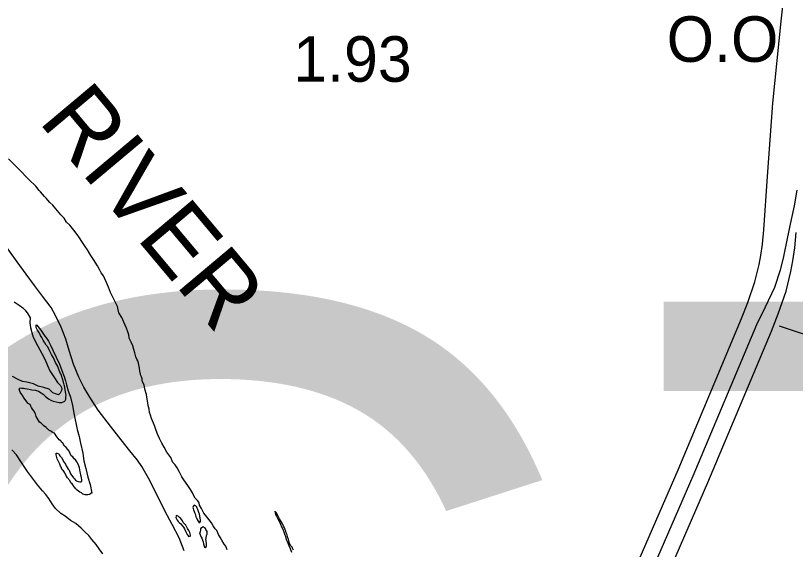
# Model space of a CAD drawing. Extents: x 31699 to 244310, y -8841 to 11474.
# Drawn here: x 103265.1 to 103747.3, y 0.3 to 330.2 of the extents above; entities that cross this region are included whole.
import ezdxf

# ---------------------------------------------------------------- set-up
doc = ezdxf.new("R2010")
doc.units = 0
for name, color, linetype in [('B_Logo', 7, 'Continuous'), ('R_Border', 7, 'Continuous'), ('R_Draft', 7, 'Continuous'), ('R_Logo', 7, 'Continuous'), ('R_XS_EARTHWORK_STAGE1', 7, 'Continuous'), ('R_XS_EARTHWORK_STAGE2', 7, 'Continuous'), ('S_WALL', 7, 'Continuous'), ('S_WALL_ANNOT', 7, 'Continuous')]:
    doc.layers.add(name, color=color, linetype=linetype)

msp = doc.modelspace()

# ---------------------------------------------------------------- linework, layer by layer
at = {"layer": 'B_Logo'}
msp.add_lwpolyline([(103748.16, 222.36), (103746.61, 212.64), (103744.7, 204.12), (103742.25, 192.44), (103740.05, 181.24), (103737.87, 172.85), (103734.47, 162.16), (103728.56, 149.95), (103723.29, 139.09), (103683.94, 45.46), (103620.47, -100.58)], dxfattribs=at)
at = {"layer": 'R_Draft'}
for points in [[(103277.65, 224.72), (103273.23, 228.97), (103266.96, 235.45), (103260.64, 241.73)], [(103283.04, 218.49), (103281.75, 219.93), (103280.52, 221.24), (103279.63, 222.16), (103277.65, 224.72)], [(103390.6, 9.5), (103389.55, 11.89), (103388.52, 13), (103387.35, 14.91), (103386.18, 16.69), (103384.81, 18.54), (103383.38, 20.31), (103381.59, 22.74), (103380.07, 25.45), (103378.76, 27.63), (103378.82, 27.7), (103378.67, 28.89), (103378.46, 29.42), (103377.57, 30.47), (103376.14, 31.91), (103375.17, 33.7), (103374.41, 35.15), (103373.23, 37.2), (103372.06, 39.04), (103370.27, 41.74), (103369.24, 43.33), (103368, 45.04), (103367.03, 46.75), (103366.2, 48.34), (103364.95, 50.65), (103363.78, 52.56), (103362.35, 53.94), (103361.02, 57.05), (103358.56, 60.34), (103356.96, 63.38), (103355.44, 65.88), (103354.05, 68.79), (103353, 71.04), (103352.08, 73.83), (103351.23, 76.15), (103350.45, 78.34), (103349.19, 81.19), (103348.49, 83.18), (103347.98, 84.97), (103347.61, 86.9), (103347.16, 89.16), (103346.8, 90.69), (103346.57, 92.09), (103346.32, 94.29), (103345.95, 96.08), (103345.02, 99.27), (103344.63, 102.07), (103343.66, 103.92), (103343.37, 104.92), (103343.29, 105.65), (103342.86, 106.98), (103342.64, 107.84), (103342.43, 108.64), (103341.86, 110.43), (103341.75, 112.23), (103341.6, 113.37), (103341.09, 115.43), (103340.66, 116.75), (103340.1, 117.94), (103339.41, 119.33), (103338.76, 121.72), (103338.25, 123.72), (103337.67, 126.04), (103336.56, 128.29), (103335.37, 130.74), (103335.06, 132.8), (103334.77, 134.2), (103333.71, 136.99), (103332.87, 138.9), (103331.97, 140.62), (103330.84, 143.61), (103328.92, 146.44), (103328.04, 150.36), (103326.5, 153.74), (103325.32, 156.18), (103323.86, 159.03), (103322.45, 162.4), (103321.33, 165.32), (103320.28, 167.5), (103319.38, 169.35), (103318.07, 171.2), (103316.97, 173.24), (103315.72, 175.62), (103313.3, 179.51), (103311.72, 181.95), (103309.65, 185.45), (103308.21, 187.56), (103306.15, 190.52), (103304.57, 192.76), (103303.25, 195), (103301.13, 197.63), (103298.54, 200.58), (103296.57, 202.54), (103295.05, 204.98), (103293.14, 207.08), (103290.07, 210.76), (103288.15, 213.05), (103286.25, 214.68), (103285.02, 216.2), (103284.06, 217.38), (103283.04, 218.49)], [(103264.2, 153.34), (103267.32, 151.13), (103269.55, 149.64), (103270.98, 148.14), (103272.62, 145.9), (103274.01, 143.39), (103274, 140.32), (103274.26, 137.45), (103275.06, 134.39), (103276.05, 131.41), (103278.56, 126.31), (103281.33, 121.43), (103283.41, 117.46), (103284.81, 114.02), (103286.28, 110.58), (103289.1, 106.23), (103290.96, 103.46), (103292.87, 101.5), (103293.77, 99.98), (103293.59, 98.57), (103292.7, 96.88), (103291.59, 95.85), (103290.44, 96.3), (103288.03, 97.11), (103285.85, 99.21), (103282.63, 100.34), (103279.15, 101.07), (103276.12, 102.54), (103272.1, 103.59), (103269.29, 104), (103266.6, 105.34), (103263.23, 107.21)], [(103292.43, 109.84), (103291.5, 112.76), (103291.01, 113.82), (103289.84, 115.8), (103289.14, 117.32), (103288.58, 118.58), (103287.4, 120.69), (103285.94, 123.67), (103285.04, 125.38), (103284.09, 126.43), (103283.12, 128.02), (103282.22, 129.6), (103281.26, 131.18), (103280.5, 132.44), (103279.8, 133.82), (103278.69, 135.87), (103277.86, 137.46), (103277.76, 138.99), (103278.16, 138.93), (103280.63, 135.85), (103283.17, 132.09), (103284.13, 130.91), (103285.44, 128.87), (103286.41, 126.82), (103286.62, 126.42), (103288.08, 123.31), (103290.24, 119.08), (103292.26, 114.65), (103293.67, 110.93), (103295.22, 107.03), (103295.94, 104.37), (103296.59, 101.98), (103297.6, 98.19), (103299.01, 94.28), (103300.32, 89.29), (103301.15, 84.5), (103303.16, 74.45), (103304.51, 70.07), (103305.33, 65.88), (103306.66, 59.83), (103307.36, 54.96), (103308.59, 50.31), (103309.83, 44.93), (103311.2, 40.28), (103312.3, 35.02)], [(103277.31, 83.99), (103276.33, 85.91), (103275.58, 87.02), (103274.96, 87.95), (103274.47, 88.87), (103274.12, 89.87), (103272.91, 90.51), (103270.72, 93.2), (103269.06, 96.04), (103268.03, 97.35), (103267.26, 99.21), (103267.71, 100.15), (103268.98, 99.91), (103269.98, 99.87), (103270.85, 99.69), (103272.19, 99.45), (103273.52, 99.21), (103275.13, 98.98), (103277.4, 98.76), (103279.35, 98.06), (103280.97, 97.03), (103282.12, 96.19), (103283.54, 94.81), (103285.37, 93.32), (103286.79, 92.48), (103288.4, 91.91), (103292.02, 90.99), (103293.75, 91.09), (103295.6, 91.86), (103296.17, 93.15), (103296.21, 94.55), (103296.33, 95.29), (103296.23, 96.56), (103295.85, 98.95), (103295.49, 100.35), (103295.34, 101.35), (103295.19, 101.95), (103294.82, 103.61), (103294.18, 105.6), (103293.54, 107.66), (103292.77, 109.18), (103292.43, 109.84), (103292.08, 110.57)], [(103312.11, 34.95), (103311.05, 34.39), (103310.72, 34.12), (103309.73, 33.9), (103308.66, 33.94), (103308.13, 34), (103306.92, 34.31), (103306.65, 34.43), (103305.9, 35.29), (103304.9, 35.53), (103304.02, 36.31), (103303.27, 36.9), (103302.45, 37.75), (103301.5, 38.67), (103300.88, 39.59), (103299.99, 40.84), (103299.31, 41.43), (103298.55, 42.75), (103297.94, 43.4), (103297.73, 43.8), (103297.18, 44.59), (103296.22, 46.1), (103295.45, 47.56), (103294.69, 48.88), (103293.95, 49.53), (103293.59, 50.39), (103293.45, 50.79), (103292.97, 51.65), (103292.54, 52.91), (103292.13, 53.7), (103291.64, 54.63), (103291.29, 55.35), (103290.74, 56.21), (103290.52, 57.14), (103290.23, 58.61), (103290.15, 59), (103290.13, 59.81), (103290.87, 59.82), (103291.67, 59.44), (103292.09, 58.78), (103292.5, 58.12), (103293.05, 57.46), (103293.52, 57.01), (103294.28, 55.69), (103294.77, 54.56), (103296.01, 52.92), (103296.36, 51.99), (103297.54, 49.94), (103298.15, 49.15), (103298.5, 48.56), (103298.85, 47.5), (103299.13, 46.97), (103299.95, 45.98), (103300.98, 44.54), (103301.46, 43.94), (103302.08, 43.02), (103302.75, 42.57), (103303.89, 42.26), (103304.83, 41.95), (103305.36, 41.96), (103306.02, 42.31), (103306, 43.31), (103305.78, 44.44), (103305.62, 45.5), (103305.54, 46.17), (103305.25, 47.37), (103305.03, 48.3), (103304.74, 49.43), (103304.52, 50.76), (103304.29, 51.89), (103303.87, 52.88), (103303.04, 54.4), (103302.15, 55.52), (103301.4, 56.17), (103300.58, 57.42), (103299.56, 58.14), (103298.87, 59.53), (103298.24, 60.92), (103297.35, 61.97), (103296.39, 63.28), (103295.44, 64.13), (103294.41, 65.84), (103293.59, 66.63), (103293.11, 67.29), (103292.1, 68), (103291.35, 68.85), (103290.86, 69.71), (103290.18, 70.5), (103289.49, 71.42), (103289.08, 72.15), (103288.47, 72.4), (103287.67, 72.78), (103286.79, 73.37), (103285.64, 74.01), (103283.94, 75.51), (103282.52, 76.62), (103280.96, 78.25), (103279.81, 78.96), (103278.49, 81.41), (103277.74, 82.46), (103277.31, 83.99)], [(103319.08, -2.39), (103316.75, 0.57), (103314.83, 3.2), (103312.24, 6.29), (103310.32, 8.79), (103307.87, 11.21), (103305.63, 13.3), (103302.3, 16.36), (103299.13, 18.03), (103295.81, 20.77), (103293.04, 22.45), (103289.78, 25.52), (103287.72, 28.48), (103285.59, 31.71), (103283.74, 34.14), (103281.83, 36.37), (103278.68, 40.18), (103276.83, 42.68), (103274.36, 45.97), (103272.45, 48.4), (103268.8, 53.94), (103265.7, 58.68), (103262.7, 61.89)], [(103379.05, 16.94), (103379.43, 17.55), (103379.48, 18.42), (103379.26, 19.75), (103379.11, 20.35), (103378.96, 21.08), (103378.74, 22.01), (103378.46, 23.01), (103378.17, 23.67), (103377.96, 24.2), (103377.75, 24.87), (103377.54, 25.33), (103377.47, 25.66), (103377.19, 26.26), (103376.91, 26.72), (103376.57, 27.05), (103376.17, 27.24), (103375.63, 27.49), (103375.04, 27.08), (103374.79, 26.21), (103375.01, 25.47), (103375.22, 24.68), (103375.51, 23.75), (103375.79, 23.15), (103376.14, 22.22), (103376.35, 21.49), (103376.86, 19.7), (103376.92, 19.77), (103377.69, 18.38), (103378.79, 16.4)], [(103373.04, 7.99), (103373.28, 9.13), (103372.91, 10.73), (103372.15, 11.98), (103371.4, 13.1), (103370.29, 15.15), (103369.54, 16.07), (103368.79, 16.92), (103368.3, 17.98), (103367.34, 19.3), (103366.46, 20.01), (103366.11, 20.47), (103365.57, 20.8), (103364.37, 21.17), (103364.37, 20.84), (103364.26, 20.03), (103364.68, 19.11), (103365.03, 18.24), (103365.64, 17.52), (103366.32, 16.8), (103367.27, 16.02), (103367.82, 15.23), (103368.91, 14.05), (103369.6, 12.93), (103370.44, 11.21), (103370.79, 10.22), (103371.21, 9.49), (103371.82, 8.63), (103372.3, 7.98)], [(103436.91, -0.19), (103436.35, 1), (103436.14, 1.59), (103435.25, 2.51), (103434.56, 3.97), (103434.13, 5.29), (103433.84, 6.42), (103433.34, 7.95), (103432.98, 9.21), (103432.42, 10.47), (103432.2, 11.47), (103431.85, 12.26), (103431.29, 13.65), (103430.8, 14.64), (103430.45, 15.57), (103429.9, 16.43), (103429.28, 17.48), (103428.38, 19.07), (103427.55, 20.72), (103426.78, 22.04), (103426.16, 23.03), (103425.42, 23.82), (103425.64, 22.75), (103425.79, 21.82), (103426.41, 20.76), (103426.76, 20.04), (103427.18, 19.11), (103428.28, 17.26), (103428.84, 15.94), (103429.55, 14.22), (103430.37, 12.83), (103430.88, 11.17), (103431.37, 9.91), (103431.94, 8.25), (103432.44, 6.46), (103433.34, 4.67), (103434.12, 2.69), (103434.82, 0.83), (103435.67, -1.56)], [(103382.5, 1.31), (103383.22, 2.33), (103383.25, 4), (103382.73, 6.46), (103382.98, 7.4), (103383.21, 8.81), (103383.59, 9.76), (103383.5, 11.22), (103383.15, 11.95), (103382.8, 12.54), (103382.59, 13.14), (103381.85, 13.59), (103381.17, 14.31), (103380.38, 13.83), (103379.92, 13.55), (103379.46, 13.01), (103379.54, 12.27), (103379.3, 11.2), (103378.92, 10.46), (103379.27, 9.26), (103379.48, 8.8), (103379.9, 7.87), (103380.18, 7.14), (103380.74, 5.89), (103381.03, 5.02), (103381.39, 3.63), (103381.75, 2.3), (103381.96, 1.63), (103382.64, 1.38)], [(103395.93, -0.07), (103395.08, 2.18), (103394.05, 3.56), (103392.67, 5.87), (103391.91, 7.33), (103390.6, 9.5)]]:
    msp.add_lwpolyline(points, dxfattribs=at)
at = {"layer": 'R_Logo'}
msp.add_lwpolyline([(103369.42, -0.57), (103366.25, 7.45), (103362.02, 15.64), (103357.58, 23.76), (103352.79, 33.28), (103347.23, 44.26), (103343.21, 51.52), (103340.4, 55.34), (103335.75, 61.25), (103330.34, 68.02), (103323.84, 76.5), (103316.1, 86.36), (103311.01, 94.27), (103307.21, 100.6), (103304.22, 106.68), (103300.99, 114.77), (103298.15, 123.26), (103296.14, 130.23), (103293.18, 137.72), (103289.77, 144.86), (103287.2, 149.82), (103281.79, 156.85), (103276.79, 163.3), (103271.58, 170.33), (103266.02, 178.1), (103260.33, 186.13)], dxfattribs=at)
at = {"layer": 'R_XS_EARTHWORK_STAGE1'}
msp.add_line((103754.23, 132.58), (103737.6, 138.32), dxfattribs=at)
at = {"layer": 'R_XS_EARTHWORK_STAGE2'}
for points in [[(103521.84, -307.39), (103540.82, -258.86), (103545.53, -248.33), (103550.26, -237), (103554.27, -226.65), (103559.44, -214.4), (103611.32, -96.55), (103674.75, 49.39), (103714.07, 142.97), (103717.92, 152.82), (103722.33, 165.55), (103724.97, 176.28), (103726.06, 181.98), (103727.08, 189.01), (103727.84, 197.81), (103730.08, 230.83), (103733.36, 276.02), (103738.47, 326.72), (103740.61, 345.27)], [(103541.68, -311.57), (103559.27, -266.59), (103563.89, -256.27), (103568.82, -244.47), (103572.81, -234.15), (103577.81, -222.32), (103629.62, -104.6), (103693.14, 41.53), (103732.51, 135.22), (103736.69, 145.9), (103741.53, 159.87), (103744.52, 172.01), (103745.79, 178.67), (103746.95, 186.71), (103747.77, 196.08)]]:
    msp.add_lwpolyline(points, dxfattribs=at)

# ---------------------------------------------------------------- texts
at = {"layer": 'R_Border'}
msp.add_text('WASHINGTON', height=500, dxfattribs=at).set_placement((100456.36, -346.53))
at = {"layer": 'R_Draft'}
msp.add_text('RIVER', height=42.24, rotation=310, dxfattribs=at).set_placement((103278.66, 264.92))
at = {"layer": 'S_WALL'}
msp.add_text('1.93', height=28.16, dxfattribs=at).set_placement((103436.78, 289.33))
at = {"layer": 'S_WALL_ANNOT'}
msp.add_text('O.O', height=28.16, dxfattribs=at).set_placement((103667.75, 301.62))

doc.saveas('drawing.dxf')
